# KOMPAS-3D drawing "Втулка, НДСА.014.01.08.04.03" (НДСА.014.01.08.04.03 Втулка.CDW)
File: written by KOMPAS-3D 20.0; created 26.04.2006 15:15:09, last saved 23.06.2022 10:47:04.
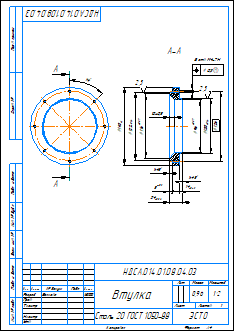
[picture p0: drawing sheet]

Sheet 1: A4, portrait

Document properties: Автор: Устинов А.В.; Организация: ЭСТО-Вакуум; Полное имя файла: НДСА.014.01.08.04.03 Втулка.m3d; 245694451935: <item xmlns="http://appius.ru/pdm" xmlns:xs="http://www.w3.org/2001/XMLSchema" xmlns:xsi="http://www.w3.org/2001/XMLSchema-instance" xsi:type="item">  <element xmlns:d2p1="http://v8.1c.ru/8.1/data/enterprise/current-config" xsi:type="d2p1:CatalogRef.aps_Элемен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; PLM_CDWXDTO: <item xmlns="http://appius.ru/pdm" xmlns:xs="http://www.w3.org/2001/XMLSchema" xmlns:xsi="http://www.w3.org/2001/XMLSchema-instance" xsi:type="item">  <element xmlns:d2p1="http://v8.1c.ru/8.1/data/enterprise/current-config" xsi:type="d2p1:CatalogRef.aps_Элемен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; Масса: 0.959708

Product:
- Part/product: Втулка  | designation НДСА.014.01.08.04.03
    Материал: Сталь 20 ГОСТ 1050-88 (density 7859 kg/m3)
    Масса: 0.959708

Title block, sheet 1: Наименование: Втулка; designation: НДСА.014.01.08.04.03; Материал: Сталь 20 ГОСТ 1050-88; Масса: 0,96; scale: 1:2; Количество листов документа: 1; organisation: ЭСТО; Форматы листов документа: A4; stored path: D:\WorkPDM\Устинов А.В\8b0af0dc-f3da-4f92-ad11-61854faa3fd1\УКРД.789.01.03.10.02 Втулка.cdw; Разработал: Волкова; Разработал, date: 16.01.2020
Table, sheet 1:
  0^Material:V399CD8922A934364BF9D3DB1A16B3F75

Views: Вид 1, Разрез А-А
Referenced files in E:\НДСА.014.01.08.00.00 Гидроподъемник\: НДСА.014.01.08.04.03 Втулка.m3d
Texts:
  НДСА.014.01.08.04.03 Втулка
Dimensions and other numbers on the sheet: 1; 140; 24; 14; 5; 122; 100; 96; 116; 10±0,5; 126; -7Н; 8 отв.; 4; 2,5; 1:2; 0,96; 16.01.2020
